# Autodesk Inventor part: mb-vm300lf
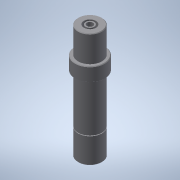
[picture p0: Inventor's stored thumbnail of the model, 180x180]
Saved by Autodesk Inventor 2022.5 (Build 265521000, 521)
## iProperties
Created: 2016-12
Part Number: mb-vm300lf
Material: 一般
Document SubType Name: Modeling
Designer: imaocorp
Density: 1 g/cm^3
Appearance: 既定
Author: imaocorp
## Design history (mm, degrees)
node "mb-vm300lf.x_t1"
node "mb-vm300lf"
node "Base1"
